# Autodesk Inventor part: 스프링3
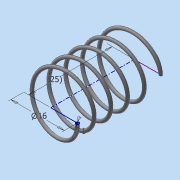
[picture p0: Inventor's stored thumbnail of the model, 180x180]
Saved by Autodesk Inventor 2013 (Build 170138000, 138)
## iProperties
Created: 2015-11
Part Number: 스프링3
Material: 강철, 탄소
Document SubType Name: Modeling
Designer: dgall
Density: 7.87 g/cm^3
Mass: 1.54771 g
Surface Area: 7.8879 cm^2
Volume: 0.19666 cm^3
Author: dgall
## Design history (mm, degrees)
sketch "스케치1"
  geometry: L1 (8, 0)-(0, 0); L2 (0, 0)-(0, 16.67); L3 (0, 16.67)-(8, 16.67); C1 r 0.5 at (8, 0)
  constraints: 6 end point, 1 centre point, 1 coincident, 1 horizontal, 1 parallel, 1 perpendicular, 1 vertical alignment
  dimensions: "d5" = 16 diameter of L1.start L2; "d7" = 16.66987 distance of L1.end L2.end (derived); "d8" = 1 diameter of C1
feature "코일1" pitch "d9" = 10; turns "d11" = 5; dims "d10" = 16.66987 (= d7), "d12" = 0, angle "d13" = 90 deg, angle "d14" = 90 deg, "d15" = 0, "d16" = 0
sketch "스케치2"
  geometry: L1 (-10, 0)-(10, 0); L2 (10, 0)-(10, -5); L3 (10, -5)-(-10, -5); L4 (-10, -5)-(-10, 0); L5 (-10, 30)-(10, 30); L6 (10, 30)-(10, 25); L7 (10, 25)-(-10, 25); L8 (-10, 25)-(-10, 30); 4 further points
  constraints: 16 end point, 4 parallel, 3 midpoint, 2 horizontal, 2 perpendicular, 1 coincident, 1 vertical alignment
  dimensions: "d17" = 25 distance between parallel lines of L7 L1; "d18" = 5 distance of L7.end L5.start; "d19" = 5 distance of L3.end L1.start; "d20" = 20 distance of L2.end L3.end; "d21" = 20 distance of L5.start L5.end
extrude "돌출1" cut sketch "스케치2" stored distance "d22" = 30; taper "d23" = 0 deg
node "솔리드1"
